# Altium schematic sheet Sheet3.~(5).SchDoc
size A4
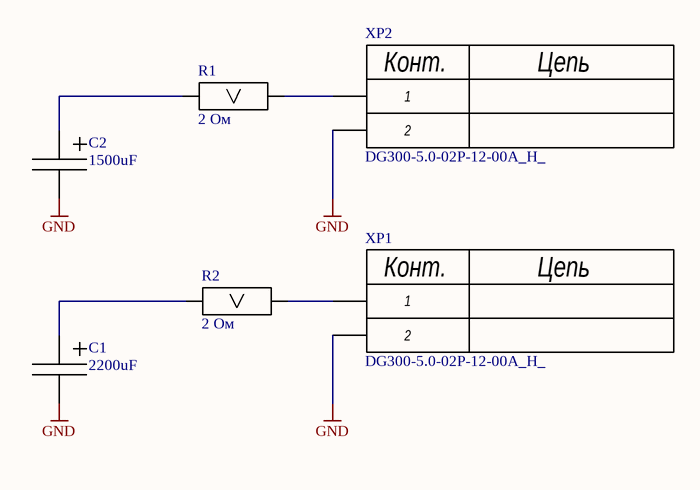
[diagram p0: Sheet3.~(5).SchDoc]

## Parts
C1  2200uF  [K50-104-63V-2200uF]
C2  1500uF  [K50-98-63V-1500uF]
R1  2 Ом  [SQP 5W2]
R2  2 Ом  [SQP 5W2]
XP1  DG300-5.0-02P-12-00A_H_  [DG3005002P1200AH]
XP2  DG300-5.0-02P-12-00A_H_  [DG3005002P1200AH]

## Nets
GND: C1.1 C2.1 XP1.2 XP2.2
NetC1_2: C1.2 R2.1
NetC2_2: C2.2 R1.1
NetR1_2: R1.2 XP2.1
NetR2_2: R2.2 XP1.1

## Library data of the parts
C1 = K50-104-63V-2200uF
C2 = K50-98-63V-1500uF
R1 R2 = SQP 5W
XP1 XP2 = DG300-5.0-02P-12-00A_H_: Клеммник винтовой, 2-контактный, 5мм, прямой; Manufacturer_Name: Degson; Manufacturer_Part_Number: DG300-5.0-02P-12-00A(H)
